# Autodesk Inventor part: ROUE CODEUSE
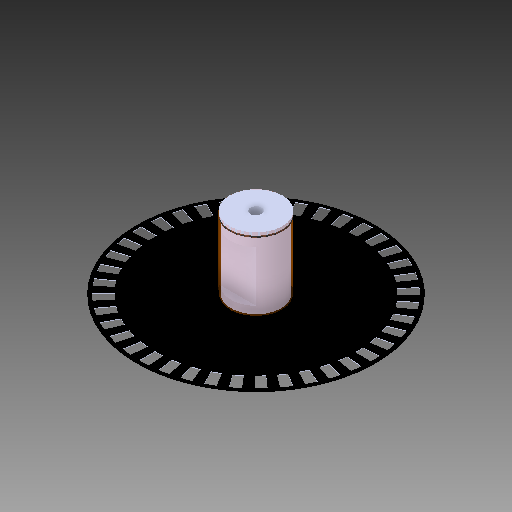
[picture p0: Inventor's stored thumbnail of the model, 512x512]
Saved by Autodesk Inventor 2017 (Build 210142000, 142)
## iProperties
Created: 2013-10
Part Number: ROUE CODEUSE
Material: Générique
Document SubType Name: Modeling
Designer: Bruno
Density: 1 g/cm^3
Appearance: Par défaut
Mass: 6.43183 g
Surface Area: 79.9554 cm^2
Volume: 6.43183 cm^3
Sending System: SolidWorks 2013
Last Author: JG
Last Saved: 2014-02-15
Author: Bruno
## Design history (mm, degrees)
feature "Enlèv. mat.-Extru.2"
sketch "Esquisse1"
  geometry: C1 r 7.561 at (0, 0); A1 r 56 centre (-50.164, 39.033) between (-103.875, 23.187) and (3.838, 24.208) reference; 1 further point
  constraints: 1 centre point, 1 coincident, 1 tangent
feature "SrfExtrusion1" sketch "Esquisse1" dims "d0" = 22, "d1" = 0
node "Solide1"
node "Référence1"
body "Srf1"
